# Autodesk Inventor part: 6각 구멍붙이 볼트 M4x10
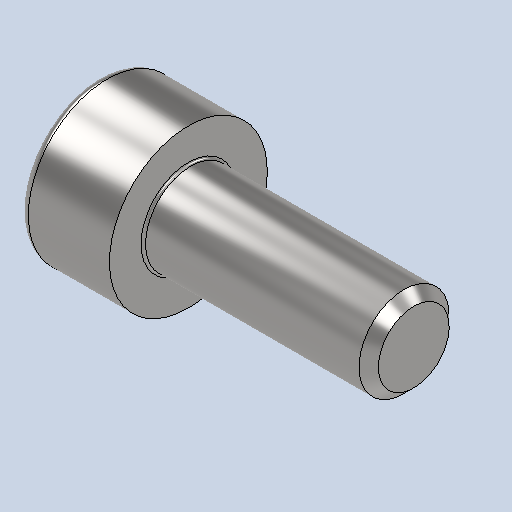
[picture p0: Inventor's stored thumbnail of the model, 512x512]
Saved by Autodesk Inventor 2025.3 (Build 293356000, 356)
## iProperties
Created: 2026-01
Part Number: 6각 구멍붙이 볼트 M4x10
Material: 강철, 연강
Description: 6각머리 태핑 나사
Document SubType Name: Modeling
Designer: pc6
Density: 7.85 g/cm^3
Appearance: 기본값
Author: jhkim
Sending System: Autodesk Inventor 2026
Preprocessor: ST-DEVELOPER v20.1
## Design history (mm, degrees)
feature "Solid1"
node "솔리드1"
